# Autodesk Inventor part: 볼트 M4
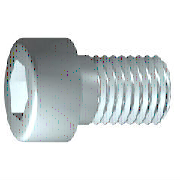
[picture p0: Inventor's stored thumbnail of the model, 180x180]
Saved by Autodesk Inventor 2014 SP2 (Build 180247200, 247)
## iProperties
IsCustomPart: 1
Created: 2012-02
Part Number: 볼트 M4
Material: 강철, 연강
Description: 6각머리 태핑 나사
Document SubType Name: Modeling
Standard: KS B 1003
Designer: mduedu
Standards Organization: KS
Language: ko-KR
Size Designation: M 4 x 10
Categories: <MemberInstance><Categories><Category DisplayName="조임쇠" InternalName="e4da775c-781d-43d5-af7c-5136215cf5a6" Mnemonic="FSTN"><Category DisplayName="볼트" InternalN
Density: 1 g/cm^3
Appearance: 강철
Author: mduedu
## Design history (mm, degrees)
sketch "스케치1"
  geometry: L1 (-1, 0)-(10, 0); L2 (10, 0)-(10, 2); L3 (10, 2)-(1.75, 2); L4 (1.75, 2)-(1.32, 2); L5 (1.32, 2)-(0, 2); L6 (0, 2)-(0, 3.5); L7 (0, 3.5)-(-4, 3.5); L8 (-4, 3.5)-(-4, 1.732); L9 (-4, 1.732)-(-2, 1.732); L10 (-2, 1.732)-(-1, 0); L11 (-6.8, 0)-(12.8, 0) reference; L12 (0, -0.7)-(0, 4.2) reference; L13 (1.75, 2)-(0, 2)
  constraints: 22 end point, 6 parallel, 2 collinear, 2 perpendicular, 1 horizontal, 1 point on line
  dimensions: "d1" = 8.25 distance from line of L3.end L2 (= GEL); "d2" = 0.42952 distance of L4.end L3.end (computed from GAL); "d3" = 4 distance between parallel lines of L8 L6 (= KOH); "d4" = 2 distance of L8.end L9.end (= INTI); "d5" = 60 deg angle of L10 L1; "d6" = 4 diameter of L3 L1 (= GD); "d7" = 4 diameter of L5 L1 (= BDM); "d8" = 3.4641 diameter of L9 L1 (= 1.1547 x SW); "d9" = 7 diameter of L7 L1 (= KOD); "d26" = 10 distance between parallel lines of L12 L2 (= NLG)
revolve "본체" sketch "스케치1" stored, may be unused: angle "d10" = 90 deg
sketch "스케치2"
  geometry: L1 (0, -4.9)-(0, 4.9) reference; L2 (-4.9, 0)-(4.9, 0) reference; L3 (1.732, 0)-(0.866, -1.5); L4 (0.866, -1.5)-(-0.866, -1.5); L5 (-0.866, -1.5)-(-1.732, 0); L6 (-1.732, 0)-(-0.866, 1.5); L7 (-0.866, 1.5)-(0.866, 1.5); L8 (0.866, 1.5)-(1.732, 0); 2 further points
  constraints: 12 end point, 1 coincident, 1 horizontal alignment, 1 point on line, 12 other
extrude "슬롯" join sketch "스케치2" stored distance "d11" = 10; taper "d12" = 0 deg
workplane "Work Plane1"
fillet "Fillet2" dims "d30" = 0.1 (= R)
body "Solid1"
fillet "모깎기1" dims "d17" = 0.4 (= RR)
feature "스레드" dims "d13" = 8.25 (= GEL), "d14" = 0
chamfer "모따기1" distance "d15" = 0.42941 (= -0.5 x SPD + 0.5 x GD); stored, may be unused: second distance "d16" = 0.42941 (= GUL), angle "d27" = 45 deg
other parameters: "GD" = 4 (= NND) [user parameter; used in 2 equation terms], "NLG" = 10 [user parameter; used in 1 equation term], "GEL" = 8.25 [user parameter; used in 2 equation terms], "KOD" = 7 [user parameter; used in 1 equation term], "KOH" = 4 [user parameter; used in 1 equation term], "INTI" = 2 [user parameter; used in 1 equation term], "GAL" = 0.42941 (= 0.61345 x PTC) [user parameter; used in 1 equation term], "GUL" = 0.42941 (= 0.61345 x PTC) [user parameter; used in 1 equation term], "BDM" = 4 (= NND) [user parameter; used in 1 equation term], "SW" = 3 [user parameter; used in 2 equation terms], "RR" = 0.4 [user parameter; used in 1 equation term], "SPD" = 3.14117 (= NND - 1.2269 x PTC) [user parameter; used in 1 equation term], "d19" = 0, "d28" = 0, "d29" = 0, "R" = 0.1 [user parameter; used in 1 equation term], "PHH" = 0.2 [user parameter], "GD1" = 3.14117 (= THREADDIA - 1.2269 x PTC) [user parameter], "THREADDIA" = 4 [user parameter; used in 1 equation term], "FAWI" = 45 deg [user parameter], "TPU" = 14.28571 (computed from PTC) [user parameter], "PTC" = 0.7 [user parameter; used in 5 equation terms], "NND" = 4 [user parameter; used in 3 equation terms], "TOA" = 30 deg [user parameter], "E0" = 3.465 (= 1.155 x SW) [user parameter]
